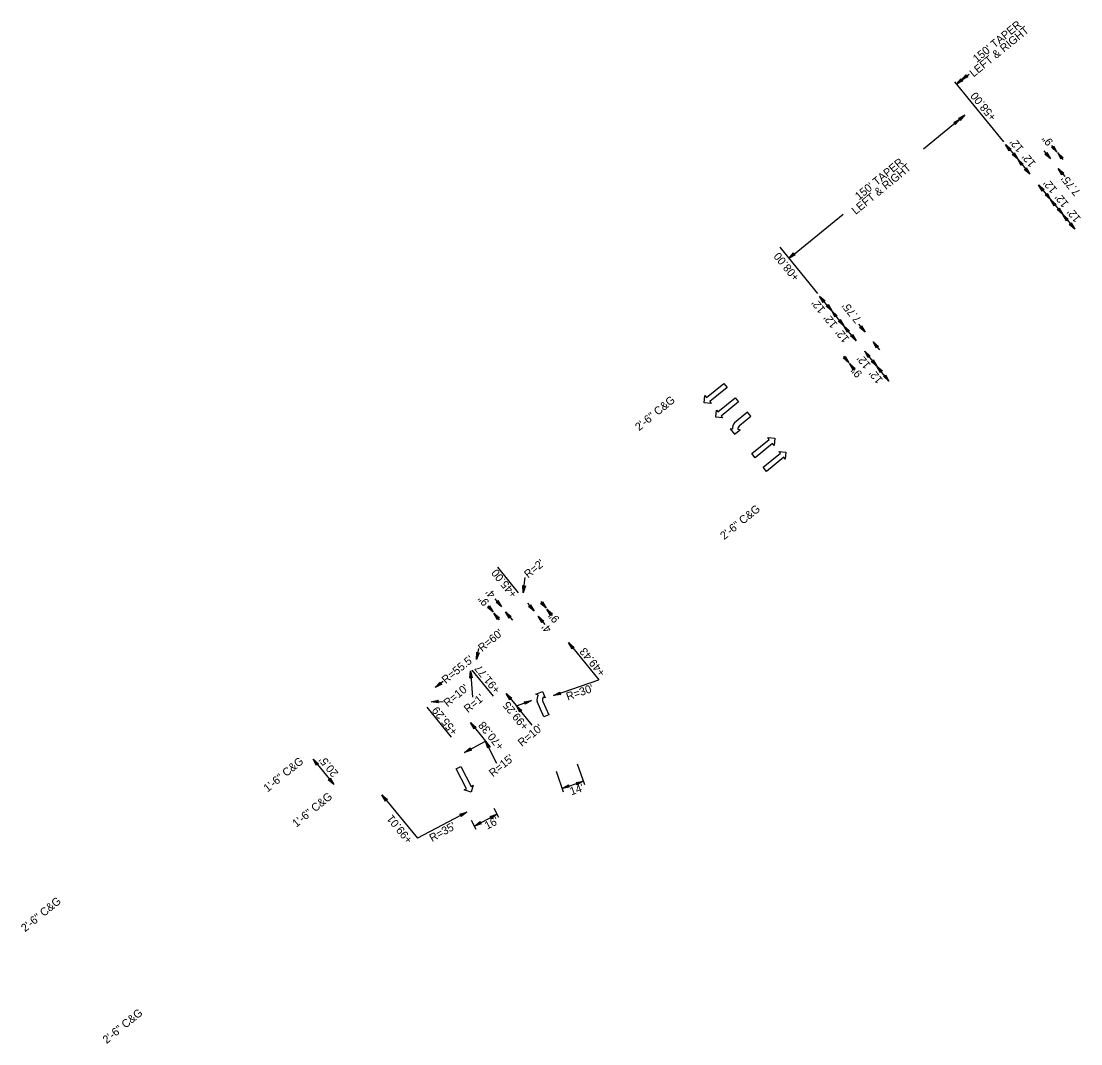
# Model space of a CAD drawing. Extents: x 2320991 to 2332664, y 598057 to 612602.
# Drawn here: x 2325031 to 2325694, y 600734 to 601374 of the extents above; entities that cross this region are included whole.
import ezdxf

# ---------------------------------------------------------------- set-up
doc = ezdxf.new("R2010")
doc.units = 0
for name, color, linetype in [('Prop Dimension', 7, 'Continuous'), ('Prop Dimension Text', 7, 'Continuous'), ('Prop Lane Arrow CELL', 7, 'Continuous'), ('Prop Terminator CELL', 7, 'Continuous')]:
    doc.layers.add(name, color=color, linetype=linetype)

msp = doc.modelspace()

# ---------------------------------------------------------------- linework, layer by layer
at = {"layer": 'Prop Dimension'}
for p, q in [((2325615.98, 601334.07), (2325623.81, 601340.47)), ((2325614.71, 601335.64), (2325645.39, 601298.05)), ((2325595.31, 601293.81), (2325621.25, 601314.98)), ((2325646.64, 601296.48), (2325654.22, 601287.19)), ((2325670.56, 601292.45), (2325674.67, 601287.42)), ((2325675.43, 601295.76), (2325678.74, 601291.71)), ((2325679.21, 601291.13), (2325682.52, 601287.07)), ((2325654.22, 601287.19), (2325661.81, 601277.89)), ((2325679.57, 601281.42), (2325683.68, 601276.38)), ((2325667.19, 601271.31), (2325674.78, 601262.01)), ((2325674.78, 601262.01), (2325682.37, 601252.71)), ((2325511.19, 601225.2), (2325545.19, 601252.96)), ((2325682.37, 601252.71), (2325689.96, 601243.42)), ((2325505.47, 601232.22), (2325529.14, 601203.21)), ((2325538, 601192.37), (2325530.41, 601201.67)), ((2325545.58, 601183.07), (2325538, 601192.37)), ((2325553.21, 601173.73), (2325545.62, 601183.03)), ((2325554.79, 601184.14), (2325558.9, 601179.11)), ((2325563.8, 601173.1), (2325567.91, 601168.07)), ((2325566.17, 601157.86), (2325558.59, 601167.15)), ((2325545.33, 601164.06), (2325548.64, 601160)), ((2325549.11, 601159.42), (2325552.43, 601155.36)), ((2325573.76, 601148.56), (2325566.17, 601157.86)), ((2325342.36, 601016.13), (2325329.24, 601032.2)), ((2325345.12, 601016.21), (2325346.52, 601025.67)), ((2325323.04, 601008.08), (2325326.35, 601004.02)), ((2325327.57, 601012.44), (2325331.68, 601007.41)), ((2325347.91, 601009.68), (2325352.02, 601004.64)), ((2325356.25, 601010.66), (2325359.56, 601006.6)), ((2325326.83, 601003.44), (2325330.14, 600999.39)), ((2325334.21, 601004.31), (2325338.41, 600999.17)), ((2325354.55, 601001.54), (2325358.74, 600996.4)), ((2325360.03, 601006.02), (2325363.35, 601001.97)), ((2325315.99, 600974.42), (2325317.5, 600981.35)), ((2325373.46, 600985.04), (2325392.44, 600961.8)), ((2325312.25, 600967.46), (2325313.57, 600950.92)), ((2325313.15, 600967.74), (2325326.41, 600951.5)), ((2325295.14, 600960.74), (2325290.22, 600957.05)), ((2325364.12, 600951.9), (2325392.44, 600961.8)), ((2325334.59, 600953.3), (2325340.91, 600945.55)), ((2325287.65, 600948.07), (2325295.1, 600948.24)), ((2325340.91, 600945.55), (2325348.46, 600948.19)), ((2325284.89, 600944.67), (2325300.1, 600926.04)), ((2325350.75, 600933.5), (2325340.91, 600945.55)), ((2325312.23, 600935.04), (2325321.71, 600923.42)), ((2325308.45, 600916.42), (2325321.71, 600923.42)), ((2325328.73, 600909.54), (2325321.71, 600923.42)), ((2325213.88, 600912.2), (2325226.84, 600896.32)), ((2325369.5, 600893.85), (2325382.72, 600898.47)), ((2325256.94, 600889.91), (2325279.08, 600862.8)), ((2325310.03, 600879.13), (2325279.08, 600862.8)), ((2325314.66, 600870.37), (2325328.81, 600877.84))]:
    msp.add_line(p, q, dxfattribs=at)
at = {"layer": 'Prop Dimension Text'}
for p, q in [((2325378.99, 600909.34), (2325383.44, 600896.35)), ((2325365.77, 600904.72), (2325370.23, 600891.74)), ((2325326.83, 600881.58), (2325329.82, 600875.92)), ((2325312.68, 600874.11), (2325315.67, 600868.45))]:
    msp.add_line(p, q, dxfattribs=at)
at = {"layer": 'Prop Lane Arrow CELL'}
for p, q in [((2325459.67, 601138.27), (2325470.54, 601147.09)), ((2325470.54, 601147.09), (2325472.62, 601144.52)), ((2325458.29, 601134.96), (2325458.72, 601139.43)), ((2325458.72, 601139.43), (2325459.67, 601138.27)), ((2325472.62, 601144.52), (2325461.74, 601135.7)), ((2325462.69, 601134.54), (2325458.29, 601134.96)), ((2325461.74, 601135.7), (2325462.69, 601134.54)), ((2325466.87, 601129.22), (2325477.74, 601138.04)), ((2325479.82, 601135.48), (2325468.95, 601126.65)), ((2325477.74, 601138.04), (2325479.82, 601135.48)), ((2325465.5, 601125.91), (2325465.93, 601130.38)), ((2325469.9, 601125.49), (2325465.5, 601125.91)), ((2325465.93, 601130.38), (2325466.87, 601129.22)), ((2325468.95, 601126.65), (2325469.9, 601125.49)), ((2325485.46, 601129.05), (2325477.28, 601122.38)), ((2325480.46, 601120.71), (2325487.54, 601126.5)), ((2325487.54, 601126.5), (2325485.46, 601129.05)), ((2325475.94, 601118.57), (2325474.46, 601118.72)), ((2325474.46, 601118.72), (2325477.21, 601115.28)), ((2325477.21, 601115.28), (2325480.72, 601118.09)), ((2325480.72, 601118.09), (2325479.25, 601118.24)), ((2325498.97, 601112.02), (2325498.03, 601113.18)), ((2325498.03, 601113.18), (2325502.43, 601112.76)), ((2325502.43, 601112.76), (2325502, 601108.29)), ((2325488.1, 601103.2), (2325498.97, 601112.02)), ((2325501.05, 601109.46), (2325490.18, 601100.64)), ((2325502, 601108.29), (2325501.05, 601109.46)), ((2325490.18, 601100.64), (2325488.1, 601103.2)), ((2325495.1, 601094.63), (2325505.97, 601103.45)), ((2325508.05, 601100.89), (2325497.18, 601092.07)), ((2325505.97, 601103.45), (2325505.02, 601104.61)), ((2325505.02, 601104.61), (2325509.42, 601104.19)), ((2325508.99, 601099.72), (2325508.05, 601100.89)), ((2325509.42, 601104.19), (2325508.99, 601099.72)), ((2325497.18, 601092.07), (2325495.1, 601094.63)), ((2325353.16, 600952.8), (2325357.18, 600954.59)), ((2325357.18, 600954.59), (2325359.01, 600950.47)), ((2325354.54, 600952.25), (2325353.16, 600952.8)), ((2325358.15, 600938.56), (2325353.98, 600948.25)), ((2325357.56, 600948.27), (2325361.18, 600939.87)), ((2325359.01, 600950.47), (2325357.63, 600951.02)), ((2325361.18, 600939.87), (2325358.15, 600938.56)), ((2325303.3, 600906.1), (2325306.24, 600907.6)), ((2325306.24, 600907.6), (2325312.64, 600895.15)), ((2325309.7, 600893.64), (2325303.3, 600906.1)), ((2325312.64, 600895.15), (2325313.97, 600895.84)), ((2325313.97, 600895.84), (2325312.65, 600891.62)), ((2325308.37, 600892.96), (2325309.7, 600893.64)), ((2325312.65, 600891.62), (2325308.37, 600892.96))]:
    msp.add_line(p, q, dxfattribs=at)
for centre, radius, start, end in [((2325481.17, 601118.87), 5.25, 137.90406, 183.21576), ((2325482.51, 601118.18), 3.27, 129.22799, 178.88617), ((2325359.04, 600949.57), 5.25, 149.32823, 194.63992), ((2325360.55, 600949.57), 3.27, 153.65782, 203.316)]:
    msp.add_arc(centre, radius, start, end, dxfattribs=at)
at = {"layer": 'Prop Terminator CELL'}
for points in [[(2325619.96, 601336.32), (2325615.98, 601334.07), (2325618.98, 601337.56), (2325619.04, 601336.57)], [(2325623.02, 601338.82), (2325619.04, 601336.57), (2325622.04, 601340.05), (2325622.1, 601339.07)], [(2325614.22, 601310.24), (2325618.19, 601312.49), (2325615.19, 601309), (2325615.13, 601309.99)], [(2325617.28, 601312.74), (2325621.25, 601314.98), (2325618.25, 601311.5), (2325618.19, 601312.49)], [(2325648.88, 601292.51), (2325646.64, 601296.48), (2325650.12, 601293.48), (2325649.13, 601293.42)], [(2325651.98, 601291.16), (2325654.22, 601287.19), (2325650.74, 601290.19), (2325651.73, 601290.25)], [(2325672.43, 601291.39), (2325674.67, 601287.42), (2325671.19, 601290.42), (2325672.17, 601290.48)], [(2325676.49, 601295.68), (2325678.74, 601291.71), (2325675.26, 601294.71), (2325676.24, 601294.77)], [(2325681.46, 601287.15), (2325679.21, 601291.13), (2325682.69, 601288.13), (2325681.71, 601288.07)], [(2325656.47, 601283.21), (2325654.22, 601287.19), (2325657.71, 601284.19), (2325656.72, 601284.13)], [(2325659.57, 601281.87), (2325661.81, 601277.89), (2325658.33, 601280.89), (2325659.32, 601280.95)], [(2325681.82, 601277.44), (2325679.57, 601281.42), (2325683.05, 601278.42), (2325682.07, 601278.36)], [(2325669.43, 601267.33), (2325667.19, 601271.31), (2325670.67, 601268.31), (2325669.69, 601268.25)], [(2325672.53, 601265.99), (2325674.78, 601262.01), (2325671.3, 601265.01), (2325672.28, 601265.07)], [(2325677.02, 601258.03), (2325674.78, 601262.01), (2325678.26, 601259.01), (2325677.28, 601258.95)], [(2325680.12, 601256.69), (2325682.37, 601252.71), (2325678.89, 601255.71), (2325679.87, 601255.77)], [(2325684.61, 601248.74), (2325682.37, 601252.71), (2325685.85, 601249.72), (2325684.87, 601249.66)], [(2325687.71, 601247.4), (2325689.96, 601243.42), (2325686.47, 601246.42), (2325687.46, 601246.48)], [(2325515.17, 601227.45), (2325511.19, 601225.2), (2325514.19, 601228.68), (2325514.25, 601227.7)], [(2325532.65, 601197.69), (2325530.41, 601201.67), (2325533.89, 601198.67), (2325532.9, 601198.61)], [(2325535.75, 601196.35), (2325538, 601192.37), (2325534.51, 601195.37), (2325535.5, 601195.43)], [(2325540.24, 601188.39), (2325538, 601192.37), (2325541.48, 601189.37), (2325540.49, 601189.31)], [(2325543.34, 601187.05), (2325545.58, 601183.07), (2325542.1, 601186.07), (2325543.09, 601186.13)], [(2325547.86, 601179.05), (2325545.62, 601183.03), (2325549.1, 601180.03), (2325548.12, 601179.97)], [(2325556.65, 601183.08), (2325558.9, 601179.11), (2325555.42, 601182.11), (2325556.4, 601182.17)], [(2325550.96, 601177.71), (2325553.21, 601173.73), (2325549.73, 601176.73), (2325550.71, 601176.79)], [(2325566.04, 601169.13), (2325563.8, 601173.1), (2325567.28, 601170.1), (2325566.3, 601170.04)], [(2325560.83, 601163.18), (2325558.59, 601167.15), (2325562.07, 601164.15), (2325561.08, 601164.09)], [(2325546.39, 601163.98), (2325548.64, 601160), (2325545.16, 601163), (2325546.14, 601163.06)], [(2325551.36, 601155.44), (2325549.11, 601159.42), (2325552.59, 601156.42), (2325551.61, 601156.36)], [(2325563.93, 601161.83), (2325566.17, 601157.86), (2325562.69, 601160.86), (2325563.68, 601160.92)], [(2325568.42, 601153.88), (2325566.17, 601157.86), (2325569.66, 601154.86), (2325568.67, 601154.8)], [(2325571.52, 601152.54), (2325573.76, 601148.56), (2325570.28, 601151.56), (2325571.27, 601151.62)], [(2325346.55, 601020.55), (2325345.12, 601016.21), (2325344.99, 601020.8), (2325345.7, 601020.11)], [(2325324.11, 601008), (2325326.35, 601004.02), (2325322.87, 601007.02), (2325323.86, 601007.08)], [(2325329.44, 601011.38), (2325331.68, 601007.41), (2325328.2, 601010.41), (2325329.19, 601010.47)], [(2325349.77, 601008.62), (2325352.02, 601004.64), (2325348.53, 601007.64), (2325349.52, 601007.7)], [(2325357.31, 601010.58), (2325359.56, 601006.6), (2325356.08, 601009.6), (2325357.06, 601009.66)], [(2325329.07, 600999.47), (2325326.83, 601003.44), (2325330.31, 601000.44), (2325329.33, 601000.38)], [(2325336.46, 601000.33), (2325334.21, 601004.31), (2325337.7, 601001.31), (2325336.71, 601001.25)], [(2325356.79, 600997.57), (2325354.55, 601001.54), (2325358.03, 600998.54), (2325357.04, 600998.48)], [(2325362.28, 601002.05), (2325360.03, 601006.02), (2325363.52, 601003.02), (2325362.53, 601002.96)], [(2325375.71, 600981.06), (2325373.46, 600985.04), (2325376.95, 600982.04), (2325375.96, 600981.98)], [(2325317.71, 600978.65), (2325315.99, 600974.42), (2325316.17, 600979.01), (2325316.83, 600978.28)], [(2325311.83, 600962.91), (2325312.25, 600967.46), (2325313.4, 600963.01), (2325312.56, 600963.52)], [(2325294.29, 600959.13), (2325290.22, 600957.05), (2325293.36, 600960.41), (2325293.38, 600959.42)], [(2325336.83, 600949.32), (2325334.59, 600953.3), (2325338.07, 600950.3), (2325337.09, 600950.24)], [(2325368.62, 600952.66), (2325364.12, 600951.9), (2325368.12, 600954.15), (2325367.84, 600953.21)], [(2325292.17, 600947.4), (2325287.65, 600948.07), (2325292.15, 600948.97), (2325291.6, 600948.16)], [(2325345.85, 600948.1), (2325350.35, 600948.85), (2325346.34, 600946.6), (2325346.62, 600947.55)], [(2325343.16, 600941.58), (2325340.91, 600945.55), (2325344.39, 600942.55), (2325343.41, 600942.49)], [(2325314.47, 600931.07), (2325312.23, 600935.04), (2325315.71, 600932.04), (2325314.72, 600931.98)], [(2325323.05, 600919.06), (2325321.71, 600923.42), (2325324.47, 600919.75), (2325323.49, 600919.9)], [(2325312.79, 600917.84), (2325308.45, 600916.42), (2325312.07, 600919.24), (2325311.94, 600918.27)], [(2325216.13, 600908.22), (2325213.88, 600912.2), (2325217.36, 600909.2), (2325216.38, 600909.14)], [(2325224.6, 600900.3), (2325226.84, 600896.32), (2325223.36, 600899.32), (2325224.35, 600899.38)], [(2325373.99, 600894.68), (2325369.5, 600893.85), (2325373.47, 600896.17), (2325373.21, 600895.22)], [(2325378.23, 600897.64), (2325382.72, 600898.47), (2325378.75, 600896.15), (2325379.01, 600897.1)], [(2325259.19, 600885.94), (2325256.94, 600889.91), (2325260.43, 600886.91), (2325259.44, 600886.85)], [(2325305.69, 600877.72), (2325310.03, 600879.13), (2325306.4, 600876.32), (2325306.54, 600877.29)], [(2325324.49, 600876.35), (2325328.81, 600877.84), (2325325.23, 600874.95), (2325325.35, 600875.93)], [(2325318.98, 600871.86), (2325314.66, 600870.37), (2325318.24, 600873.25), (2325318.12, 600872.27)]]:
    msp.add_lwpolyline(points, close=True, dxfattribs=at)

# ---------------------------------------------------------------- texts
at = {"layer": 'Prop Dimension'}
for s, p in [('+58.00', (2325641.18, 601313.73)), ('+08.00', (2325518.22, 601213.51)), ('+45.00', (2325341.75, 601015.53)), ('+49.43', (2325396.91, 600966.42)), ('+91.77', (2325331.24, 600955.76)), ('+99.25', (2325348.99, 600932.81)), ('+55.29', (2325304.67, 600929.61)), ('+70.38', (2325333.61, 600920.35)), ('+99.01', (2325276.42, 600861.94))]:
    msp.add_text(s, height=5, rotation=129.22799, dxfattribs=at).set_placement(p)
at = {"layer": 'Prop Dimension Text'}
for s, rotation, p in [('LEFT & RIGHT', 39.22799, (2325626.63, 601338.27)), ("150' TAPER", 39.22799, (2325628.7, 601347.34)), ("12'", 129.22799, (2325658.24, 601293.99)), ('9"', 129.22799, (2325676.68, 601298.12)), ('LEFT & RIGHT', 39.22799, (2325552.97, 601252.33)), ("150' TAPER", 39.22799, (2325555.05, 601261.39)), ("12'", 129.22799, (2325665.83, 601284.7)), ("12'", 129.22799, (2325679.16, 601268.37)), ("7.75'", 129.22799, (2325693.8, 601266.77)), ("12'", 129.22799, (2325686.38, 601259.52)), ("12'", 129.22799, (2325693.97, 601250.23)), ("12'", 129.22799, (2325534.32, 601193.36)), ("7.75'", 129.22799, (2325556.84, 601187.24)), ("12'", 129.22799, (2325541.91, 601184.07)), ("12'", 129.22799, (2325549.35, 601174.95)), ("12'", 129.22799, (2325562.66, 601158.65)), ('9"', 129.22799, (2325557.37, 601153.21)), ("12'", 129.22799, (2325570.25, 601149.35)), ('2\'-6" C&G', 39.22799, (2325417.6, 601117.15)), ('2\'-6" C&G', 39.22799, (2325470.8, 601049.09)), ("R=2'", 39.22799, (2325348.28, 601025.03)), ("4'", 129.22799, (2325328.25, 601015.38)), ('9"', 129.22799, (2325324.3, 601010.44)), ('9"', 129.22799, (2325368.23, 600999.88)), ("R=60'", 39.22799, (2325319.51, 600979.07)), ("4'", 129.22799, (2325363.28, 600993.7)), ("R=55.5'", 39.22799, (2325296.8, 600959.04)), ("R=10'", 39.22799, (2325297.94, 600944.61)), ("R=30'", 19.25787, (2325373.06, 600948.77)), ("R=1'", 39.22799, (2325310.66, 600940.89)), ("R=10'", 39.22799, (2325344.36, 600919.75)), ("R=15'", 39.22799, (2325326.3, 600900.76)), ('1\'-6" C&G', 39.22799, (2325185.42, 600891.34)), ("20.5'", 129.22799, (2325230.02, 600903.49)), ("14'", 19.25776, (2325375.3, 600889.52)), ('1\'-6" C&G', 39.22799, (2325203.41, 600869.31)), ("16'", 27.82254, (2325322.69, 600868.01)), ("R=35'", 29.32401, (2325288.28, 600860.29)), ('2\'-6" C&G', 39.22799, (2325033.91, 600803.91)), ('2\'-6" C&G', 39.22799, (2325084.9, 600734.05))]:
    msp.add_text(s, height=5, rotation=rotation, dxfattribs=at).set_placement(p)

doc.saveas('drawing.dxf')
